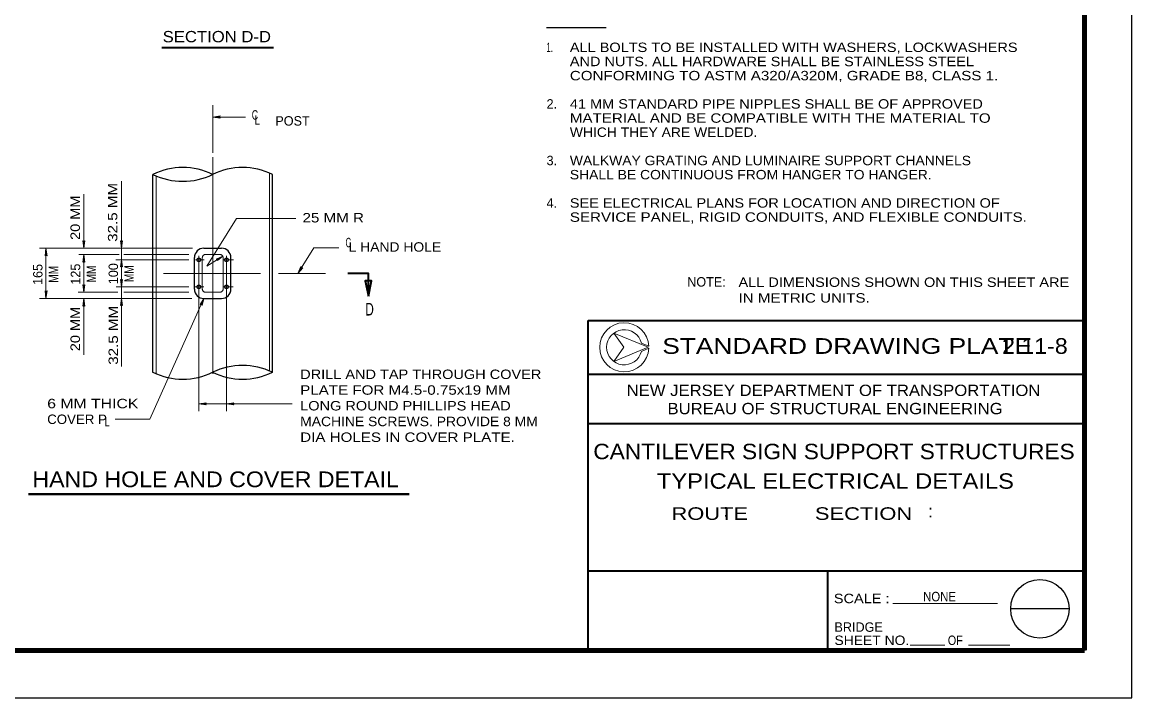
# Model space of a CAD drawing. Extents: x 312601.858 to 312602.699, y 144420.109 to 144420.704.
# Drawn here: x 312602.3461 to 312602.6988, y 144420.1095 to 144420.3244 of the extents above; entities that cross this region are included whole.
import ezdxf
from ezdxf.enums import TextEntityAlignment as Align

# ---------------------------------------------------------------- set-up
doc = ezdxf.new("R2010")
doc.units = 0
doc.header["$LTSCALE"] = 0.0012
for name, pattern in [('LONG_DASH_SHORT_DASH', [9.9, 6, -1.2, 1.5, -1.2]), ('LONG_DASHED', [7.5, 6, -1.5]), ('MEDIUM_DASHED', [4.5, 3, -1.5])]:
    doc.linetypes.add(name, pattern=pattern)
for name, color, linetype, lineweight in [('1', 7, 'Continuous', 25), ('2', 7, 'Continuous', 25), ('39', 7, 'Continuous', 13)]:
    doc.layers.add(name, color=color, linetype=linetype, lineweight=lineweight)
doc.layers.add('4', color=7, linetype='Continuous')

msp = doc.modelspace()

# ---------------------------------------------------------------- hatches: boundary and pattern name
at = {"layer": '39'}
for points in [[(312602.4089, 144420.2942), (312602.4091, 144420.2939), (312602.4067, 144420.2942), (312602.4091, 144420.2946)], [(312602.3657, 144420.2547), (312602.3661, 144420.2549), (312602.3657, 144420.2525), (312602.3654, 144420.2549)], [(312602.3537, 144420.2503), (312602.3534, 144420.2501), (312602.3537, 144420.2525), (312602.3541, 144420.2501)], [(312602.3657, 144420.2483), (312602.3654, 144420.2481), (312602.3657, 144420.2505), (312602.3661, 144420.2481)], [(312602.4349, 144420.2463), (312602.4353, 144420.2463), (312602.4337, 144420.2445), (312602.4347, 144420.2467)], [(312602.3657, 144420.2407), (312602.3661, 144420.2409), (312602.3657, 144420.2385), (312602.3654, 144420.2409)], [(312602.3537, 144420.2387), (312602.3541, 144420.2389), (312602.3537, 144420.2365), (312602.3534, 144420.2389)], [(312602.3657, 144420.2343), (312602.3654, 144420.2341), (312602.3657, 144420.2365), (312602.3661, 144420.2341)]]:
    msp.add_hatch(color=256, dxfattribs=at).paths.add_polyline_path(points)

# ---------------------------------------------------------------- linework, layer by layer
at = {"layer": '1'}
for p, q in [((312602.5128, 144420.3227), (312602.5317, 144420.3227)), ((312602.3877, 144420.213), (312602.3877, 144420.276)), ((312602.4257, 144420.213), (312602.4257, 144420.276)), ((312602.4039, 144420.2525), (312602.4095, 144420.2525)), ((312602.4009, 144420.2395), (312602.4009, 144420.2495)), ((312602.4125, 144420.2395), (312602.4125, 144420.2495)), ((312602.4039, 144420.2365), (312602.4095, 144420.2365))]:
    msp.add_line(p, q, dxfattribs=at)
at = {"layer": '1', "lineweight": 35}
msp.add_line((312602.3905, 144420.3163), (312602.426, 144420.3163), dxfattribs=at)
at = {"layer": '1', "lineweight": 13}
for p, q in [((312602.4067, 144420.2828), (312602.4067, 144420.298)), ((312602.4067, 144420.2942), (312602.4171, 144420.2942)), ((312602.3657, 144420.2525), (312602.3657, 144420.2697)), ((312602.4048, 144420.2468), (312602.4143, 144420.262)), ((312602.4143, 144420.262), (312602.4331, 144420.262)), ((312602.3516, 144420.2525), (312602.4003, 144420.2525)), ((312602.3537, 144420.2365), (312602.3537, 144420.2525)), ((312602.3642, 144420.2505), (312602.377, 144420.2505)), ((312602.3657, 144420.2385), (312602.3657, 144420.2505)), ((312602.3785, 144420.2505), (312602.3991, 144420.2505)), ((312602.3759, 144420.2488), (312602.3991, 144420.2488)), ((312602.3777, 144420.2402), (312602.3777, 144420.2488)), ((312602.4048, 144420.2468), (312602.4099, 144420.25)), ((312602.4276, 144420.2445), (312602.4425, 144420.2445)), ((312602.376, 144420.2402), (312602.3991, 144420.2402)), ((312602.3517, 144420.2365), (312602.4001, 144420.2365)), ((312602.3639, 144420.2385), (312602.3765, 144420.2385)), ((312602.3657, 144420.2186), (312602.3657, 144420.2365)), ((312602.3784, 144420.2385), (312602.3991, 144420.2385)), ((312602.4039, 144420.2365), (312602.3867, 144420.1981)), ((312602.4023, 144420.2007), (312602.4023, 144420.2315)), ((312602.4111, 144420.2007), (312602.4111, 144420.2315)), ((312602.543, 144420.2197), (312602.5453, 144420.2207)), ((312602.3757, 144420.1981), (312602.3867, 144420.1981))]:
    msp.add_line(p, q, dxfattribs=at)
at = {"layer": '1', "linetype": 'LONG_DASH_SHORT_DASH', "lineweight": 13}
for p, q in [((312602.4067, 144420.2125), (312602.4067, 144420.2815)), ((312602.4012, 144420.2488), (312602.404, 144420.2488)), ((312602.4023, 144420.2315), (312602.4023, 144420.2501)), ((312602.41, 144420.2488), (312602.4133, 144420.2488)), ((312602.4111, 144420.2315), (312602.4111, 144420.2501)), ((312602.3911, 144420.2445), (312602.4219, 144420.2445)), ((312602.4011, 144420.2402), (312602.4039, 144420.2402)), ((312602.4099, 144420.2402), (312602.4132, 144420.2402))]:
    msp.add_line(p, q, dxfattribs=at)
at = {"layer": '1', "linetype": 'LONG_DASHED', "lineweight": 13}
for p, q in [((312602.3887, 144420.2126), (312602.3887, 144420.2755)), ((312602.4247, 144420.2135), (312602.4247, 144420.2764))]:
    msp.add_line(p, q, dxfattribs=at)
at = {"layer": '1', "linetype": 'MEDIUM_DASHED', "lineweight": 13}
for p, q in [((312602.4044, 144420.2505), (312602.409, 144420.2505)), ((312602.4034, 144420.2395), (312602.4034, 144420.2495)), ((312602.41, 144420.2395), (312602.41, 144420.2495)), ((312602.4044, 144420.2385), (312602.409, 144420.2385))]:
    msp.add_line(p, q, dxfattribs=at)
at = {"layer": '1', "lineweight": 40}
msp.add_line((312602.3482, 144420.1743), (312602.4691, 144420.1743), dxfattribs=at)
at = {"layer": '1', "lineweight": 13}
for points in [[(312602.3777, 144420.2488), (312602.3777, 144420.2525), (312602.3777, 144420.2738)], [(312602.4337, 144420.2445), (312602.4388, 144420.2526), (312602.4468, 144420.2526)], [(312602.3777, 144420.2149), (312602.3777, 144420.2365), (312602.3777, 144420.2402)], [(312602.5451, 144420.221), (312602.5342, 144420.2255), (312602.5451, 144420.221)], [(312602.5453, 144420.2213), (312602.543, 144420.2223), (312602.5429, 144420.2223)], [(312602.4023, 144420.203), (312602.4111, 144420.203), (312602.4319, 144420.203)]]:
    msp.add_lwpolyline(points, dxfattribs=at)
for points in [[(312602.378, 144420.2548), (312602.3777, 144420.2525), (312602.3774, 144420.2548), (312602.3777, 144420.2545)], [(312602.3774, 144420.2466), (312602.3777, 144420.2488), (312602.378, 144420.2466), (312602.3777, 144420.2468)], [(312602.4078, 144420.249), (312602.4099, 144420.25), (312602.4082, 144420.2486), (312602.4082, 144420.2489)], [(312602.378, 144420.2425), (312602.3777, 144420.2402), (312602.3774, 144420.2425), (312602.3777, 144420.2422)], [(312602.3774, 144420.2343), (312602.3777, 144420.2365), (312602.378, 144420.2343), (312602.3777, 144420.2345)], [(312602.4027, 144420.2346), (312602.4039, 144420.2365), (312602.4033, 144420.2343), (312602.4031, 144420.2347)], [(312602.5451, 144420.221), (312602.5342, 144420.2255), (312602.5374, 144420.221), (312602.5342, 144420.2165)], [(312602.5374, 144420.221), (312602.5342, 144420.2165), (312602.5451, 144420.221), (312602.5342, 144420.2255)], [(312602.4046, 144420.2027), (312602.4023, 144420.203), (312602.4046, 144420.2033), (312602.4043, 144420.203)], [(312602.4134, 144420.2027), (312602.4111, 144420.203), (312602.4134, 144420.2033), (312602.4131, 144420.203)]]:
    msp.add_lwpolyline(points, close=True, dxfattribs=at)
at = {"layer": '1'}
for centre in [(312602.402286, 144420.248801), (312602.411078, 144420.248801), (312602.402286, 144420.240209), (312602.411078, 144420.240209)]:
    msp.add_circle(centre, 0.000599, dxfattribs=at)
for centre, radius, start, end in [((312602.397191, 144420.256582), 0.021591, 63.92269, 116.07731), ((312602.397191, 144420.295368), 0.021591, 243.92269, 296.07731), ((312602.416173, 144420.256582), 0.021591, 63.92269, 116.07731), ((312602.403884, 144420.2495), 0.002997, 90, 180), ((312602.409479, 144420.2495), 0.002997, 0, 90), ((312602.403884, 144420.239509), 0.002997, 180, 270), ((312602.409479, 144420.239509), 0.002997, 270, 0), ((312602.416173, 144420.193641), 0.021591, 63.92269, 116.07731), ((312602.397191, 144420.232427), 0.021591, 243.92269, 296.07731), ((312602.416173, 144420.232427), 0.021591, 243.92269, 296.07731)]:
    msp.add_arc(centre, radius, start, end, dxfattribs=at)
at = {"layer": '1', "linetype": 'MEDIUM_DASHED', "lineweight": 13}
for centre, start, end in [((312602.4044, 144420.2495), 90, 180), ((312602.409, 144420.2495), 0, 90), ((312602.4044, 144420.2395), 180, 270), ((312602.409, 144420.2395), 270, 0)]:
    msp.add_arc(centre, 0.001, start, end, dxfattribs=at)
at = {"layer": '1', "lineweight": 13}
for radius, start, end in [(0.007803, 2.21392, 357.78608), (0.0056, 13.69411, 346.30589)]:
    msp.add_arc((312602.5375, 144420.221), radius, start, end, dxfattribs=at)
at = {"layer": '2'}
msp.add_line((312602.6839, 144420.2307), (312602.6839, 144420.2656), dxfattribs=at)
at = {"layer": '39', "lineweight": 25}
for p, q in [((312602.6988, 144420.1095), (312602.6988, 144420.7035)), ((312602.6988, 144420.1095), (312602.6988, 144420.7035)), ((312602.6988, 144420.1095), (312602.6988, 144420.7035)), ((312602.6789, 144420.1378), (312602.6603, 144420.1378)), ((312602.452, 144420.1245), (312602.6838, 144420.1245)), ((312601.8578, 144420.1095), (312602.6988, 144420.1095))]:
    msp.add_line(p, q, dxfattribs=at)
at = {"layer": '39', "lineweight": 158}
for p, q in [((312602.6838, 144420.1247), (312602.6838, 144420.6645)), ((312601.9088, 144420.1245), (312602.6838, 144420.1245))]:
    msp.add_line(p, q, dxfattribs=at)
at = {"layer": '39', "lineweight": 35}
for p, q in [((312602.526, 144420.1245), (312602.526, 144420.2295)), ((312602.526, 144420.2295), (312602.6838, 144420.2295)), ((312602.6838, 144420.2295), (312602.6838, 144420.1245)), ((312602.526, 144420.2124), (312602.6838, 144420.2124)), ((312602.526, 144420.1968), (312602.6838, 144420.1968)), ((312602.526, 144420.1499), (312602.6838, 144420.1499)), ((312602.6022, 144420.1248), (312602.6022, 144420.1499))]:
    msp.add_line(p, q, dxfattribs=at)
at = {"layer": '39'}
for p, q in [((312602.6022, 144420.1499), (312602.6838, 144420.1499)), ((312602.6022, 144420.1248), (312602.6022, 144420.1499)), ((312602.6022, 144420.1248), (312602.6022, 144420.1499)), ((312602.6229, 144420.1395), (312602.6561, 144420.1395)), ((312602.6284, 144420.1263), (312602.6394, 144420.1263)), ((312602.6469, 144420.1263), (312602.66, 144420.1263))]:
    msp.add_line(p, q, dxfattribs=at)
for points in [[(312602.4089, 144420.2942), (312602.4091, 144420.2939), (312602.4067, 144420.2942), (312602.4091, 144420.2946)], [(312602.3657, 144420.2547), (312602.3661, 144420.2549), (312602.3657, 144420.2525), (312602.3654, 144420.2549)], [(312602.3537, 144420.2503), (312602.3534, 144420.2501), (312602.3537, 144420.2525), (312602.3541, 144420.2501)], [(312602.3657, 144420.2483), (312602.3654, 144420.2481), (312602.3657, 144420.2505), (312602.3661, 144420.2481)], [(312602.4349, 144420.2463), (312602.4353, 144420.2463), (312602.4337, 144420.2445), (312602.4347, 144420.2467)], [(312602.3657, 144420.2407), (312602.3661, 144420.2409), (312602.3657, 144420.2385), (312602.3654, 144420.2409)], [(312602.4552, 144420.2421), (312602.4562, 144420.2373), (312602.4572, 144420.2421)], [(312602.3537, 144420.2387), (312602.3541, 144420.2389), (312602.3537, 144420.2365), (312602.3534, 144420.2389)], [(312602.3657, 144420.2343), (312602.3654, 144420.2341), (312602.3657, 144420.2365), (312602.3661, 144420.2341)], [(312602.5451, 144420.221), (312602.5342, 144420.2255), (312602.5374, 144420.221), (312602.5342, 144420.2165)]]:
    msp.add_lwpolyline(points, close=True, dxfattribs=at)
at = {"layer": '39', "lineweight": 35}
msp.add_lwpolyline([(312602.4562, 144420.2375), (312602.4562, 144420.2445), (312602.4496, 144420.2445)], dxfattribs=at)
msp.add_lwpolyline([(312602.4562, 144420.2373), (312602.4572, 144420.2421), (312602.4552, 144420.2421)], close=True, dxfattribs=at)
at = {"layer": '39', "lineweight": 25}
msp.add_circle((312602.6696, 144420.1378), 0.0093, dxfattribs=at)

# ---------------------------------------------------------------- texts
at = {"layer": '1'}
for s, height, width, p in [('1.', 0.003, 0.6, (312602.5128, 144420.3149)), ('ALL BOLTS TO BE INSTALLED WITH WASHERS, LOCKWASHERS', 0.003, 1.15, (312602.5202, 144420.3149)), ('AND NUTS. ALL HARDWARE SHALL BE STAINLESS STEEL ', 0.003, 1.15, (312602.5202, 144420.3104)), ('CONFORMING TO ASTM A320/A320M, GRADE B8, CLASS 1.', 0.003, 1.2, (312602.5202, 144420.3059)), ('41 MM STANDARD PIPE NIPPLES SHALL BE OF APPROVED', 0.003, 1.15, (312602.5202, 144420.2969)), ('C', 0.003, 0.7, (312602.4191, 144420.2934)), ('L', 0.003, 0.75, (312602.42, 144420.2918)), ('MATERIAL AND BE COMPATIBLE WITH THE MATERIAL TO ', 0.003, 1.2, (312602.5202, 144420.2924)), ('WHICH THEY ARE WELDED.', 0.003, 1.1, (312602.5202, 144420.2879)), ('WALKWAY GRATING AND LUMINAIRE SUPPORT CHANNELS', 0.003, 1.1, (312602.5202, 144420.2789)), ('SHALL BE CONTINUOUS FROM HANGER TO HANGER.', 0.003, 1.1, (312602.5202, 144420.2744)), ('SEE ELECTRICAL PLANS FOR LOCATION AND DIRECTION OF', 0.003, 1.15, (312602.5202, 144420.2654)), ('SERVICE PANEL, RIGID CONDUITS, AND FLEXIBLE CONDUITS. ', 0.003, 1.2, (312602.5202, 144420.2609)), ('D', 0.004, 0.7, (312602.4552, 144420.2311)), ('DRILL AND TAP THROUGH COVER ', 0.003, 1.15, (312602.4345, 144420.2109)), ('PLATE FOR M4.5-0.75x19 MM', 0.003, 1.2, (312602.4345, 144420.2059)), ('6 MM THICK ', 0.003, 1.25, (312602.3541, 144420.2016)), ('LONG ROUND PHILLIPS HEAD ', 0.003, 1.15, (312602.4345, 144420.2009)), ('COVER P', 0.003, 1.05, (312602.3541, 144420.1966)), ('MACHINE SCREWS. PROVIDE 8 MM', 0.003, 1.1, (312602.4345, 144420.1959)), ('DIA HOLES IN COVER PLATE.', 0.003, 1.2, (312602.4345, 144420.1909))]:
    msp.add_text(s, height=height, dxfattribs=dict(at, width=width)).set_placement(p)
for s, p in [('2.', (312602.5128, 144420.2969)), ('POST', (312602.4266, 144420.2915)), ('3.', (312602.5128, 144420.2789)), ('4.', (312602.5128, 144420.2654))]:
    msp.add_text(s, height=0.003, dxfattribs=at).set_placement(p)
at = {"layer": '2', "width": 1.1}
for s, height, p in [('SECTION D-D', 0.0036, (312602.3908, 144420.318)), ('HAND HOLE AND COVER DETAIL', 0.005, (312602.3494, 144420.1765))]:
    msp.add_text(s, height=height, dxfattribs=at).set_placement(p)
at = {"layer": '2'}
for s, width, p in [('32.5 MM', 1.2, (312602.3764, 144420.2639)), ('20 MM', 1.15, (312602.3645, 144420.2622)), ('MM', 0.8, (312602.3696, 144420.2443)), ('MM', 0.8, (312602.3816, 144420.2444)), ('MM', 0.8, (312602.3576, 144420.2442)), ('20 MM', 1.15, (312602.3645, 144420.2268)), ('32.5 MM', 1.2, (312602.3766, 144420.2248))]:
    msp.add_text(s, height=0.003, rotation=90, dxfattribs=dict(at, width=width)).set_placement(p, align=Align.CENTER)
for s, height, width, p in [('25 MM R', 0.003, 1.2, (312602.445, 144420.2607)), ('C', 0.003, 0.6, (312602.4498, 144420.2528)), ('L HAND HOLE', 0.003, 1.1, (312602.4646, 144420.2514)), ('2.11-8', 0.005, 1.1, (312602.668, 144420.2189)), ('L', 0.003, 0.75, (312602.37315, 144420.1958)), ('CANTILEVER SIGN SUPPORT STRUCTURES', 0.0049, 1.1, (312602.60415, 144420.1854)), ('TYPICAL ELECTRICAL DETAILS', 0.0049, 1.15, (312602.6046, 144420.176)), ('NONE', 0.003, 0.9, (312602.6377, 144420.1402))]:
    msp.add_text(s, height=height, dxfattribs=dict(at, width=width)).set_placement(p, align=Align.CENTER)
for s, p in [('165', (312602.3526, 144420.24415)), ('125', (312602.3646, 144420.24425)), ('100', (312602.3766, 144420.2444))]:
    msp.add_text(s, height=0.003, rotation=90, dxfattribs=at).set_placement(p, align=Align.CENTER)
at = {"layer": '39'}
for s, height, width, p in [('STANDARD DRAWING PLATE       ', 0.005, 1.25, (312602.61645, 144420.2189)), ('NEW JERSEY DEPARTMENT OF TRANSPORTATION', 0.003599, 1.1, (312602.604, 144420.2055)), ('BUREAU OF STRUCTURAL ENGINEERING', 0.0036, 1.1, (312602.6045, 144420.1997)), ('ROUTE           SECTION', 0.004, 1.3, (312602.59075, 144420.1661)), ('SCALE :', 0.003, 1.15, (312602.61295, 144420.1396)), ('OF', 0.003, 0.85, (312602.6427, 144420.1263))]:
    msp.add_text(s, height=height, dxfattribs=dict(at, width=width)).set_placement(p, align=Align.CENTER)
for p in [(312602.569737, 144420.1671), (312602.634837, 144420.1669)]:
    msp.add_text(':', height=0.004, dxfattribs=at).set_placement(p, align=Align.CENTER)
msp.add_text('BRIDGE', height=0.003, dxfattribs=at).set_placement((312602.6043, 144420.1305))
at = {"layer": '39', "width": 1.1}
msp.add_text('SHEET NO.', height=0.003, dxfattribs=at).set_placement((312602.6043, 144420.1263))
at = {"layer": '4'}
msp.add_text('NOTE:', height=0.003, dxfattribs=at).set_placement((312602.5575, 144420.2403))
for s, width, p in [('ALL DIMENSIONS SHOWN ON THIS SHEET ARE', 1.15, (312602.5738, 144420.2402)), ('IN METRIC UNITS.', 1.2, (312602.5738, 144420.2352))]:
    msp.add_text(s, height=0.003, dxfattribs=dict(at, width=width)).set_placement(p)

doc.saveas('drawing.dxf')
